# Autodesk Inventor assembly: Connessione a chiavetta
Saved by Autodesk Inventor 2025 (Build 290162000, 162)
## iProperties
ClientObjectVersion: 1
Created: 2026-05
Part Number: Connessione a chiavetta
Document SubType Name: Assembly
Designer: R5800u
Author: R5800u
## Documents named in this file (1)
- C:\Users\Ryzen5700u\Desktop\riduttore pompa\Connessione a chiavetta5.iam
